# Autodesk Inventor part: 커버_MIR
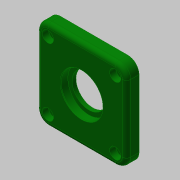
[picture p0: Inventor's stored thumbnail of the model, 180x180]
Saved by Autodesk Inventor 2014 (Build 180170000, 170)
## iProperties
Created: 2019-09
Part Number: 커버_MIR
Material: 알루미늄 6061
Document SubType Name: Modeling
Designer: kh
Density: 2.71 g/cm^3
Appearance: 알루미늄 - 평지
Author: mduedu
d1: 9.000 mm
d2: 0.00 deg
d3: 42.000 mm
d4: 3.000 mm
d5: 0.00 deg
d8: 24.000 mm
d10: 30.000 mm
d11: 5.200 mm
d17: 37.000 mm
d22: 4.000 mm
d24: 3.000 mm
d25: 3.000 mm
d27: 0.500 mm
d29: 30.00 deg
d30: 1.000 mm
d44: 64.000 mm
d45: 64.000 mm
d48: 8.000 mm
d49: 4.500 mm
d51: 8.000 mm
d52: 4.400 mm
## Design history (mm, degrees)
derived "커버.ipt"
  sketch "스케치1"
    geometry: L1 (32, -32)-(-32, -32) reference; L2 (-32, -32)-(-32, 32) reference; L3 (-32, 32)-(32, 32) reference; L4 (32, 32)-(32, -32) reference; L5 (32, -32)-(-32, 32) reference; L6 (-32, -32)-(32, 32) reference; 1 further point
  sketch "스케치2"
    geometry: C1 r 21 at (0, 0) reference; 1 further point
  sketch "스케치4"
    geometry: A1 r 8 centre (24, 24) between (32, 24) and (24, 32) reference; A2 r 8 centre (-24, 24) between (-24, 32) and (-32, 24) reference; A3 r 8 centre (-24, -24) between (-32, -24) and (-24, -32) reference; A4 r 8 centre (24, -24) between (24, -32) and (32, -24) reference; 5 further points
feature "솔리드1::커버.ipt"
tag "피쳐 태그1"
node "솔리드1"
other parameters: "d1" = 9, "d2" = 0 deg, "d3" = 42, "d4" = 3, "d5" = 0 deg, "d8" = 24, "d10" = 30, "d11" = 5.2, "d17" = 37, "d22" = 4, "d24" = 3, "d25" = 3, "d27" = 0.5, "d29" = 30 deg, "d30" = 1, "d44" = 64, "d45" = 64, "d48" = 8, "d49" = 4.5, "d51" = 8, "d52" = 4.4
